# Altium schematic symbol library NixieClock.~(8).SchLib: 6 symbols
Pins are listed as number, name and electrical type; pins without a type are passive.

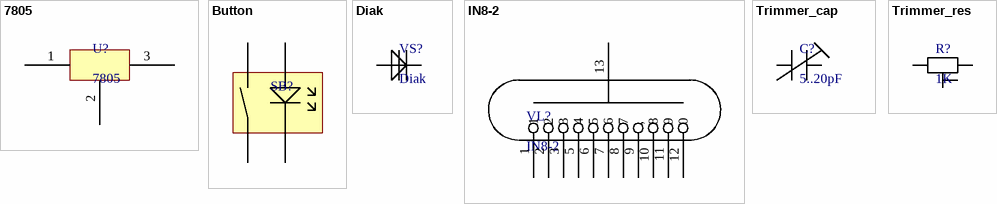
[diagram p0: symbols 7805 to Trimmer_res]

## 7805
designator U?
pins: 1 In, 2 GND, 3 Out

## Button
designator SB?  (value not drawn)
pins: 1, 2, 3, 4

## Diak
designator VS?
pins: 1, 2

## IN8-2
designator VL?
pins: 1, 2, 3, 5 4, 6 5, 7 6, 8 7, 9 ,, 10 8, 11 9, 12 0, 13

## Trimmer_cap
designator C?, comment 5..20pF
pins: 1, 2

## Trimmer_res
designator R?, comment 1K
pins: 1, 2, 3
